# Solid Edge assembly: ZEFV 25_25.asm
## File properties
Title: Zylinder
Author: bmolnar
Template: iso metric assembly.asm
Last saved by: bmolnar
Revision: 13
Application: Solid Edge
Username: bmolnar
Dokumentum tartalom típus: 1
Document Number: ZEFV 25/25
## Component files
Mutter.par
Profilrohr.par
Kolbenstange.par
Kit_2.par
Kit_1.par
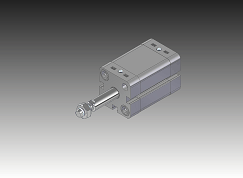
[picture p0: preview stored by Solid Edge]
